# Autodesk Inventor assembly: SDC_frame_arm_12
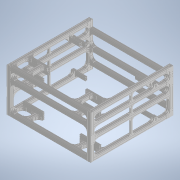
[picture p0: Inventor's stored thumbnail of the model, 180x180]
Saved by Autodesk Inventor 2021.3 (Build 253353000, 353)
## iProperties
Created: 2022-02
Part Number: SDC_frame_arm_12
Description: CAx-IF Rec.Pracs.---Model Styling and Organization---1.2---2011-12-15
Document SubType Name: Assembly
Designer: kengo
Sending System: 3D_Kernel_IO2017 Sp2 by CT CoreTechnologie
Preprocessor: STEP Interface 2017 Sp2 by CT CoreTechnologie
Title: SDC_frame_arm_12.stp
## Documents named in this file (150)
- C:\Users\kengo\Documents\S2S_frame\SDC345\frame_misumi_ver12\SDC_frame_arm_12.iam
- C:\Users\kengo\Documents\S2S_frame\SDC345\frame_misumi_ver12\HBLFSDW8-90-SET(1).iam
- C:\Users\kengo\Documents\S2S_frame\SDC345\frame_misumi_ver12\HBLFSDW8-90-SET(2).iam
- C:\Users\kengo\Documents\S2S_frame\SDC345\frame_misumi_ver12\HBLFSDW8-90-SET(3).iam
- C:\Users\kengo\Documents\S2S_frame\SDC345\frame_misumi_ver12\HBLFSDW8-90-SET(4).iam
- C:\Users\kengo\Documents\S2S_frame\SDC345\frame_misumi_ver12\HBLFSDW8-90-SET(5).iam
- C:\Users\kengo\Documents\S2S_frame\SDC345\frame_misumi_ver12\HBLFSDW8-90-SET(6).iam
- C:\Users\kengo\Documents\S2S_frame\SDC345\frame_misumi_ver12\HBLFSDW8-90-SET(7).iam
- C:\Users\kengo\Documents\S2S_frame\SDC345\frame_misumi_ver12\HBLFSDW8-90-SET(8).iam
- C:\Users\kengo\Documents\S2S_frame\SDC345\frame_misumi_ver12\HBLFSDW8-90-SET(9).iam
- C:\Users\kengo\Documents\S2S_frame\SDC345\frame_misumi_ver12\HBLFSDW8-90-SET(10).iam
- C:\Users\kengo\Documents\S2S_frame\SDC345\frame_misumi_ver12\HBLFSDW8-90-SET(11).iam
- C:\Users\kengo\Documents\S2S_frame\SDC345\frame_misumi_ver12\HBLFSDW8-90-SET(12).iam
- C:\Users\kengo\Documents\S2S_frame\SDC345\frame_misumi_ver12\HBLFSDW8-90-SET(13).iam
- C:\Users\kengo\Documents\S2S_frame\SDC345\frame_misumi_ver12\HBLFSDW8-90-SET(14).iam
- C:\Users\kengo\Documents\S2S_frame\SDC345\frame_misumi_ver12\HBLFSDW8-90-SET(15).iam
- C:\Users\kengo\Documents\S2S_frame\SDC345\frame_misumi_ver12\HBLFSDW8-90-SET(16).iam
- C:\Users\kengo\Documents\S2S_frame\SDC345\frame_misumi_ver12\HBLFSDW8-90-SET(17).iam
- C:\Users\kengo\Documents\S2S_frame\SDC345\frame_misumi_ver12\HBLFSDW8-90-SET(18).iam
- C:\Users\kengo\Documents\S2S_frame\SDC345\frame_misumi_ver12\HBLFSDW8-90-SET(19).iam
- C:\Users\kengo\Documents\S2S_frame\SDC345\frame_misumi_ver12\HBLFSDW8-90-SET(20).iam
- C:\Users\kengo\Documents\S2S_frame\SDC345\frame_misumi_ver12\HBLFSDW8-90-SET(21).iam
- C:\Users\kengo\Documents\S2S_frame\SDC345\frame_misumi_ver12\GNFS8-9090-1910.ipt
- C:\Users\kengo\Documents\S2S_frame\SDC345\frame_misumi_ver12\GNFS8-9090-1940.ipt
- C:\Users\kengo\Documents\S2S_frame\SDC345\frame_misumi_ver12\GNFS8-9090-1090.ipt
- C:\Users\kengo\Documents\S2S_frame\SDC345\frame_misumi_ver12\HBLFSDW8-90-SET(22).iam
- C:\Users\kengo\Documents\S2S_frame\SDC345\frame_misumi_ver12\HPTTD8-45-SET(1).iam
- C:\Users\kengo\Documents\S2S_frame\SDC345\frame_misumi_ver12\HPTTD8-45-SET(2).iam
- C:\Users\kengo\Documents\S2S_frame\SDC345\frame_misumi_ver12\HPTTD8-45-SET(3).iam
- C:\Users\kengo\Documents\S2S_frame\SDC345\frame_misumi_ver12\HPTLD8-45-SET(1).iam
- C:\Users\kengo\Documents\S2S_frame\SDC345\frame_misumi_ver12\HPTLD8-45-SET(2).iam
- C:\Users\kengo\Documents\S2S_frame\SDC345\frame_misumi_ver12\HPTTD8-45-SET(4).iam
- C:\Users\kengo\Documents\S2S_frame\SDC345\frame_misumi_ver12\HPTLD8-45-SET(3).iam
- C:\Users\kengo\Documents\S2S_frame\SDC345\frame_misumi_ver12\HPTLD8-45-SET(4).iam
- C:\Users\kengo\Documents\S2S_frame\SDC345\frame_misumi_ver12\HBLFSDW8-90-SET(23).iam
- C:\Users\kengo\Documents\S2S_frame\SDC345\frame_misumi_ver12\HBLFSDW8-90-SET(24).iam
- C:\Users\kengo\Documents\S2S_frame\SDC345\frame_misumi_ver12\HBLFSDW8-90-SET(25).iam
- C:\Users\kengo\Documents\S2S_frame\SDC345\frame_misumi_ver12\HBLFSDW8-90-SET(26).iam
- C:\Users\kengo\Documents\S2S_frame\SDC345\frame_misumi_ver12\HBLFSDW8-90-SET(27).iam
- C:\Users\kengo\Documents\S2S_frame\SDC345\frame_misumi_ver12\HBLFSDW8-90-SET(28).iam
- C:\Users\kengo\Documents\S2S_frame\SDC345\frame_misumi_ver12\HBLFSDW8-90-SET(29).iam
- C:\Users\kengo\Documents\S2S_frame\SDC345\frame_misumi_ver12\HBLFSDW8-90-SET(30).iam
- C:\Users\kengo\Documents\S2S_frame\SDC345\frame_misumi_ver12\HBLFSDW8-90-SET(31).iam
- C:\Users\kengo\Documents\S2S_frame\SDC345\frame_misumi_ver12\HBLFSDW8-90-SET(32).iam
- C:\Users\kengo\Documents\S2S_frame\SDC345\frame_misumi_ver12\HBLFSDW8-90-SET(33).iam
- C:\Users\kengo\Documents\S2S_frame\SDC345\frame_misumi_ver12\HBLFSDW8-90-SET(34).iam
- C:\Users\kengo\Documents\S2S_frame\SDC345\frame_misumi_ver12\HBLFSDW8-90-SET(35).iam
- C:\Users\kengo\Documents\S2S_frame\SDC345\frame_misumi_ver12\HBLFSDW8-90-SET(36).iam
- C:\Users\kengo\Documents\S2S_frame\SDC345\frame_misumi_ver12\HBLFSDW8-90-SET(37).iam
- C:\Users\kengo\Documents\S2S_frame\SDC345\frame_misumi_ver12\HBLFSDW8-90-SET(38).iam
- C:\Users\kengo\Documents\S2S_frame\SDC345\frame_misumi_ver12\HBLFSDW8-90-SET(39).iam
- C:\Users\kengo\Documents\S2S_frame\SDC345\frame_misumi_ver12\HBLFSDW8-90-SET(40).iam
- C:\Users\kengo\Documents\S2S_frame\SDC345\frame_misumi_ver12\HBLFSDW8-90-SET(41).iam
- C:\Users\kengo\Documents\S2S_frame\SDC345\frame_misumi_ver12\HBLFSDW8-90-SET(42).iam
- C:\Users\kengo\Documents\S2S_frame\SDC345\frame_misumi_ver12\HBLFSDW8-90-SET(43).iam
- C:\Users\kengo\Documents\S2S_frame\SDC345\frame_misumi_ver12\HBLFSDW8-90-SET(44).iam
- C:\Users\kengo\Documents\S2S_frame\SDC345\frame_misumi_ver12\HPTSD8-45-SET(1).iam
- C:\Users\kengo\Documents\S2S_frame\SDC345\frame_misumi_ver12\HBLFSDW8-90-SET(45).iam
- C:\Users\kengo\Documents\S2S_frame\SDC345\frame_misumi_ver12\HPTSD8-45-SET(2).iam
- C:\Users\kengo\Documents\S2S_frame\SDC345\frame_misumi_ver12\HPTSD8-45-SET(3).iam
- C:\Users\kengo\Documents\S2S_frame\SDC345\frame_misumi_ver12\HPTSD8-45-SET(4).iam
- C:\Users\kengo\Documents\S2S_frame\SDC345\frame_misumi_ver12\GNFS8-4590-360-RTP.ipt
- C:\Users\kengo\Documents\S2S_frame\SDC345\frame_misumi_ver12\HBLFSDW8-90-SET(46).iam
- C:\Users\kengo\Documents\S2S_frame\SDC345\frame_misumi_ver12\HBLFSDW8-90-SET(47).iam
- C:\Users\kengo\Documents\S2S_frame\SDC345\frame_misumi_ver12\HBLFSDW8-90-SET(48).iam
- C:\Users\kengo\Documents\S2S_frame\SDC345\frame_misumi_ver12\HBLFSDW8-90-SET(49).iam
- C:\Users\kengo\Documents\S2S_frame\SDC345\frame_misumi_ver12\HBLFSDW8-90-SET(50).iam
- C:\Users\kengo\Documents\S2S_frame\SDC345\frame_misumi_ver12\GNFS8-4590-360-LTP.ipt
- C:\Users\kengo\Documents\S2S_frame\SDC345\frame_misumi_ver12\HBLFSN8-45-SET(1).iam
- C:\Users\kengo\Documents\S2S_frame\SDC345\frame_misumi_ver12\HBLFSDW8-90-SET(51).iam
- C:\Users\kengo\Documents\S2S_frame\SDC345\frame_misumi_ver12\HBLFSDW8-90-SET(52).iam
- C:\Users\kengo\Documents\S2S_frame\SDC345\frame_misumi_ver12\HBLFSDW8-90-SET(53).iam
- C:\Users\kengo\Documents\S2S_frame\SDC345\frame_misumi_ver12\GNFS8-4545-180.ipt
- C:\Users\kengo\Documents\S2S_frame\SDC345\frame_misumi_ver12\HBLFSN8-45-SET(2).iam
- C:\Users\kengo\Documents\S2S_frame\SDC345\frame_misumi_ver12\HBLFSN8-45-SET(3).iam
- C:\Users\kengo\Documents\S2S_frame\SDC345\frame_misumi_ver12\HBLFSN8-45-SET(4).iam
- C:\Users\kengo\Documents\S2S_frame\SDC345\frame_misumi_ver12\HBLFSN8-45-SET(5).iam
- C:\Users\kengo\Documents\S2S_frame\SDC345\frame_misumi_ver12\GNFS8-4545-185.ipt
- C:\Users\kengo\Documents\S2S_frame\SDC345\frame_misumi_ver12\HBLFSN8-45-SET(6).iam
- C:\Users\kengo\Documents\S2S_frame\SDC345\frame_misumi_ver12\HBLFSN8-45-SET(7).iam
- C:\Users\kengo\Documents\S2S_frame\SDC345\frame_misumi_ver12\HBLFSN8-45-SET(8).iam
- C:\Users\kengo\Documents\S2S_frame\SDC345\frame_misumi_ver12\HBLFSN8-45-SET(9).iam
- C:\Users\kengo\Documents\S2S_frame\SDC345\frame_misumi_ver12\GNFS8-4545-365.ipt
- C:\Users\kengo\Documents\S2S_frame\SDC345\frame_misumi_ver12\HBLFSN8-45-SET(10).iam
- C:\Users\kengo\Documents\S2S_frame\SDC345\frame_misumi_ver12\HBLFSN8-45-SET(11).iam
- C:\Users\kengo\Documents\S2S_frame\SDC345\frame_misumi_ver12\HBLFSN8-45-SET(12).iam
- C:\Users\kengo\Documents\S2S_frame\SDC345\frame_misumi_ver12\HBLFSN8-45-SET(13).iam
- C:\Users\kengo\Documents\S2S_frame\SDC345\frame_misumi_ver12\HBLFSN8-45-SET(14).iam
- C:\Users\kengo\Documents\S2S_frame\SDC345\frame_misumi_ver12\HBLFSN8-45-SET(15).iam
- C:\Users\kengo\Documents\S2S_frame\SDC345\frame_misumi_ver12\HBLFSN8-45-SET(16).iam
- C:\Users\kengo\Documents\S2S_frame\SDC345\frame_misumi_ver12\HBLFSN8-45-SET(17).iam
- C:\Users\kengo\Documents\S2S_frame\SDC345\frame_misumi_ver12\HBLFSN8-45-SET(18).iam
- C:\Users\kengo\Documents\S2S_frame\SDC345\frame_misumi_ver12\HBLFSN8-45-SET(19).iam
- C:\Users\kengo\Documents\S2S_frame\SDC345\frame_misumi_ver12\HBLFSN8-45-SET(20).iam
- C:\Users\kengo\Documents\S2S_frame\SDC345\frame_misumi_ver12\HBLFSN8-45-SET(21).iam
- C:\Users\kengo\Documents\S2S_frame\SDC345\frame_misumi_ver12\HBLFSN8-45-SET(22).iam
- C:\Users\kengo\Documents\S2S_frame\SDC345\frame_misumi_ver12\HBLFSN8-45-SET(23).iam
- C:\Users\kengo\Documents\S2S_frame\SDC345\frame_misumi_ver12\HBLFSN8-45-SET(24).iam
- C:\Users\kengo\Documents\S2S_frame\SDC345\frame_misumi_ver12\HBLFSN8-45-SET(25).iam
- C:\Users\kengo\Documents\S2S_frame\SDC345\frame_misumi_ver12\HBLFSN8-45-SET(26).iam
- C:\Users\kengo\Documents\S2S_frame\SDC345\frame_misumi_ver12\HBLFSN8-45-SET(27).iam
- C:\Users\kengo\Documents\S2S_frame\SDC345\frame_misumi_ver12\HBLFSN8-45-SET(28).iam
- C:\Users\kengo\Documents\S2S_frame\SDC345\frame_misumi_ver12\HBLFSDW8-90-SET(54).iam
- C:\Users\kengo\Documents\S2S_frame\SDC345\frame_misumi_ver12\HBLFSDW8-90-SET(55).iam
- C:\Users\kengo\Documents\S2S_frame\SDC345\frame_misumi_ver12\HFS8-45180-500.ipt
- C:\Users\kengo\Documents\S2S_frame\SDC345\frame_misumi_ver12\HBLFSDW8-90-SET(56).iam
- C:\Users\kengo\Documents\S2S_frame\SDC345\frame_misumi_ver12\HBLFSDW8-90-SET(57).iam
- C:\Users\kengo\Documents\S2S_frame\SDC345\frame_misumi_ver12\GNFS8-9090-225.ipt
- C:\Users\kengo\Documents\S2S_frame\SDC345\frame_misumi_ver12\HBLFSDW8-90-SET(58).iam
- C:\Users\kengo\Documents\S2S_frame\SDC345\frame_misumi_ver12\HBLFSDW8-90-SET(59).iam
- C:\Users\kengo\Documents\S2S_frame\SDC345\frame_misumi_ver12\HBLFSDW8-90-SET(60).iam
- C:\Users\kengo\Documents\S2S_frame\SDC345\frame_misumi_ver12\HBLFSDW8-90-SET(61).iam
- C:\Users\kengo\Documents\S2S_frame\SDC345\frame_misumi_ver12\HBLFSDW8-90-SET(62).iam
- C:\Users\kengo\Documents\S2S_frame\SDC345\frame_misumi_ver12\HBLFSDW8-90-SET(63).iam
- C:\Users\kengo\Documents\S2S_frame\SDC345\frame_misumi_ver12\HBLFSDW8-90-SET(64).iam
- C:\Users\kengo\Documents\S2S_frame\SDC345\frame_misumi_ver12\HBLFSDW8-90-SET(65).iam
- C:\Users\kengo\Documents\S2S_frame\SDC345\frame_misumi_ver12\HBLFSDW8-90-SET(66).iam
- C:\Users\kengo\Documents\S2S_frame\SDC345\frame_misumi_ver12\HBLFSDW8-90-SET(67).iam
- C:\Users\kengo\Documents\S2S_frame\SDC345\frame_misumi_ver12\HBLFSDW8-90-SET(68).iam
- C:\Users\kengo\Documents\S2S_frame\SDC345\frame_misumi_ver12\HBLFSDW8-90-SET(69).iam
- C:\Users\kengo\Documents\S2S_frame\SDC345\frame_misumi_ver12\HBLFSDW8-90-SET(70).iam
- C:\Users\kengo\Documents\S2S_frame\SDC345\frame_misumi_ver12\HBLFSDW8-90-SET(71).iam
- C:\Users\kengo\Documents\S2S_frame\SDC345\frame_misumi_ver12\HBLFSDW8-90-SET(72).iam
- C:\Users\kengo\Documents\S2S_frame\SDC345\frame_misumi_ver12\HBLFSDW8-90-SET(73).iam
- C:\Users\kengo\Documents\S2S_frame\SDC345\frame_misumi_ver12\HBLFSDW8-90-SET(74).iam
- C:\Users\kengo\Documents\S2S_frame\SDC345\frame_misumi_ver12\HBLFSDW8-90-SET(75).iam
- C:\Users\kengo\Documents\S2S_frame\SDC345\frame_misumi_ver12\HBLFSDW8-90-SET(76).iam
- C:\Users\kengo\Documents\S2S_frame\SDC345\frame_misumi_ver12\HBLFSDW8-90-SET(77).iam
- C:\Users\kengo\Documents\S2S_frame\SDC345\frame_misumi_ver12\HBLFSDW8-90-SET(78).iam
- C:\Users\kengo\Documents\S2S_frame\SDC345\frame_misumi_ver12\HBLFSDW8-90-SET(79).iam
- C:\Users\kengo\Documents\S2S_frame\SDC345\frame_misumi_ver12\GNFS8-9090-369.ipt
- C:\Users\kengo\Documents\S2S_frame\SDC345\frame_misumi_ver12\HBLFSDW8-90-SET(80).iam
- C:\Users\kengo\Documents\S2S_frame\SDC345\frame_misumi_ver12\HBLFSDW8-90-SET(81).iam
- C:\Users\kengo\Documents\S2S_frame\SDC345\frame_misumi_ver12\HBLFSDW8-90-SET(82).iam
- C:\Users\kengo\Documents\S2S_frame\SDC345\frame_misumi_ver12\HBLFSDW8-90-SET(83).iam
- C:\Users\kengo\Documents\S2S_frame\SDC345\frame_misumi_ver12\HBLFSDW8-90-SET(84).iam
- C:\Users\kengo\Documents\S2S_frame\SDC345\frame_misumi_ver12\HBLFSDW8-90-SET(85).iam
- C:\Users\kengo\Documents\S2S_frame\SDC345\frame_misumi_ver12\HBLFSDW8-90-SET(86).iam
- C:\Users\kengo\Documents\S2S_frame\SDC345\frame_misumi_ver12\HBLFSDW8-90-SET(87).iam
- C:\Users\kengo\Documents\S2S_frame\SDC345\frame_misumi_ver12\HBLFSDW8-90-SET(88).iam
- C:\Users\kengo\Documents\S2S_frame\SDC345\frame_misumi_ver12\HBLFSDW8-90-SET(89).iam
- C:\Users\kengo\Documents\S2S_frame\SDC345\frame_misumi_ver12\HBLFSN8-45-SET(29).iam
- C:\Users\kengo\Documents\S2S_frame\SDC345\frame_misumi_ver12\HBLFSN8-45-SET(30).iam
- C:\Users\kengo\Documents\S2S_frame\SDC345\frame_misumi_ver12\HBLFSDW8-90-SET(90).iam
- C:\Users\kengo\Documents\S2S_frame\SDC345\frame_misumi_ver12\HBLFSDW8-90-SET(91).iam
- C:\Users\kengo\Documents\S2S_frame\SDC345\frame_misumi_ver12\HBLFSDW8-90-SET(92).iam
- C:\Users\kengo\Documents\S2S_frame\SDC345\frame_misumi_ver12\HBLFSDW8-90-SET(93).iam
- C:\Users\kengo\Documents\S2S_frame\SDC345\frame_misumi_ver12\HBLFSDW8-90-SET(94).iam
- C:\Users\kengo\Documents\S2S_frame\SDC345\frame_misumi_ver12\HBLFSDW8-90-SET(95).iam
- C:\Users\kengo\Documents\S2S_frame\SDC345\frame_misumi_ver12\HBLFSDW8-90-SET(96).iam
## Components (180 placed, 149 different names)
1. HBLFSDW8-90-SET(1) [sub-assembly]
2. HBLFSDW8-90-SET(2) [sub-assembly]
3. HBLFSDW8-90-SET(3) [sub-assembly]
4. HBLFSDW8-90-SET(4) [sub-assembly]
5. HBLFSDW8-90-SET(5) [sub-assembly]
6. HBLFSDW8-90-SET(6) [sub-assembly]
7. HBLFSDW8-90-SET(7) [sub-assembly]
8. HBLFSDW8-90-SET(8) [sub-assembly]
9. HBLFSDW8-90-SET(9) [sub-assembly]
10. HBLFSDW8-90-SET(10) [sub-assembly]
11. HBLFSDW8-90-SET(11) [sub-assembly]
12. HBLFSDW8-90-SET(12) [sub-assembly]
13. HBLFSDW8-90-SET(13) [sub-assembly]
14. HBLFSDW8-90-SET(14) [sub-assembly]
15. HBLFSDW8-90-SET(15) [sub-assembly]
16. HBLFSDW8-90-SET(16) [sub-assembly]
17. HBLFSDW8-90-SET(17) [sub-assembly]
18. HBLFSDW8-90-SET(18) [sub-assembly]
19. HBLFSDW8-90-SET(19) [sub-assembly]
20. HBLFSDW8-90-SET(20) [sub-assembly]
21. HBLFSDW8-90-SET(21) [sub-assembly]
22. GNFS8-9090-1910
23. GNFS8-9090-1910:1
24. GNFS8-9090-1940
25. GNFS8-9090-1940:1
26. GNFS8-9090-1090 — フラッシュ:1, メイト:3, メイト:6
27. GNFS8-9090-1090:1 — メイト:1, フラッシュ:2, メイト:5, フラッシュ:5
28. GNFS8-9090-1940:2 — フラッシュ:1, メイト:1, フラッシュ:2, メイト:2, フラッシュ:3, メイト:4, フラッシュ:4, メイト:6
29. GNFS8-9090-1910:2
30. GNFS8-9090-1910:3
31. GNFS8-9090-1910:4
32. GNFS8-9090-1910:5 — フラッシュ:5
33. GNFS8-9090-1910:6
34. GNFS8-9090-1910:7
35. GNFS8-9090-1090:2
36. GNFS8-9090-1090:3
37. GNFS8-9090-1940:3
38. GNFS8-9090-1940:4
39. GNFS8-9090-1940:5
40. HBLFSDW8-90-SET(22) [sub-assembly]
41. HPTTD8-45-SET(1) [sub-assembly]
42. HPTTD8-45-SET(2) [sub-assembly]
43. HPTTD8-45-SET(3) [sub-assembly]
44. HPTLD8-45-SET(1) [sub-assembly]
45. HPTLD8-45-SET(2) [sub-assembly]
46. HPTTD8-45-SET(4) [sub-assembly]
47. HPTLD8-45-SET(3) [sub-assembly]
48. HPTLD8-45-SET(4) [sub-assembly]
49. HBLFSDW8-90-SET(23) [sub-assembly]
50. HBLFSDW8-90-SET(24) [sub-assembly]
51. HBLFSDW8-90-SET(25) [sub-assembly]
52. HBLFSDW8-90-SET(26) [sub-assembly]
53. HBLFSDW8-90-SET(27) [sub-assembly]
54. HBLFSDW8-90-SET(28) [sub-assembly]
55. HBLFSDW8-90-SET(29) [sub-assembly]
56. HBLFSDW8-90-SET(30) [sub-assembly]
57. HBLFSDW8-90-SET(31) [sub-assembly]
58. HBLFSDW8-90-SET(32) [sub-assembly]
59. HBLFSDW8-90-SET(33) [sub-assembly]
60. HBLFSDW8-90-SET(34) [sub-assembly]
61. HBLFSDW8-90-SET(35) [sub-assembly]
62. HBLFSDW8-90-SET(36) [sub-assembly]
63. HBLFSDW8-90-SET(37) [sub-assembly]
64. HBLFSDW8-90-SET(38) [sub-assembly]
65. HBLFSDW8-90-SET(39) [sub-assembly] — メイト:2, フラッシュ:3, メイト:3
66. HBLFSDW8-90-SET(40) [sub-assembly] — メイト:4, フラッシュ:4, メイト:5
67. HBLFSDW8-90-SET(41) [sub-assembly]
68. HBLFSDW8-90-SET(42) [sub-assembly]
69. HBLFSDW8-90-SET(43) [sub-assembly]
70. HBLFSDW8-90-SET(44) [sub-assembly]
71. HPTSD8-45-SET(1) [sub-assembly]
72. HBLFSDW8-90-SET(45) [sub-assembly]
73. HPTSD8-45-SET(2) [sub-assembly]
74. HPTSD8-45-SET(3) [sub-assembly]
75. HPTSD8-45-SET(4) [sub-assembly]
76. GNFS8-4590-360-RTP
77. HBLFSDW8-90-SET(46) [sub-assembly]
78. HBLFSDW8-90-SET(47) [sub-assembly]
79. GNFS8-4590-360-RTP:1
80. HBLFSDW8-90-SET(48) [sub-assembly]
81. HBLFSDW8-90-SET(49) [sub-assembly]
82. GNFS8-4590-360-RTP:2
83. HBLFSDW8-90-SET(50) [sub-assembly]
84. GNFS8-4590-360-LTP
85. GNFS8-4590-360-LTP:1
86. GNFS8-4590-360-LTP:2
87. HBLFSN8-45-SET(1) [sub-assembly]
88. HBLFSDW8-90-SET(51) [sub-assembly]
89. HBLFSDW8-90-SET(52) [sub-assembly]
90. HBLFSDW8-90-SET(53) [sub-assembly]
91. GNFS8-4545-180
92. HBLFSN8-45-SET(2) [sub-assembly]
93. HBLFSN8-45-SET(3) [sub-assembly]
94. HBLFSN8-45-SET(4) [sub-assembly]
95. HBLFSN8-45-SET(5) [sub-assembly]
96. GNFS8-4545-185
97. HBLFSN8-45-SET(6) [sub-assembly]
98. HBLFSN8-45-SET(7) [sub-assembly]
99. HBLFSN8-45-SET(8) [sub-assembly]
100. HBLFSN8-45-SET(9) [sub-assembly]
101. GNFS8-4545-365
102. HBLFSN8-45-SET(10) [sub-assembly]
103. HBLFSN8-45-SET(11) [sub-assembly]
104. HBLFSN8-45-SET(12) [sub-assembly]
105. HBLFSN8-45-SET(13) [sub-assembly]
106. GNFS8-4545-365:1
107. HBLFSN8-45-SET(14) [sub-assembly]
108. HBLFSN8-45-SET(15) [sub-assembly]
109. HBLFSN8-45-SET(16) [sub-assembly]
110. HBLFSN8-45-SET(17) [sub-assembly]
111. GNFS8-4545-185:1
112. HBLFSN8-45-SET(18) [sub-assembly]
113. HBLFSN8-45-SET(19) [sub-assembly]
114. HBLFSN8-45-SET(20) [sub-assembly]
115. HBLFSN8-45-SET(21) [sub-assembly]
116. GNFS8-4545-180:1
117. HBLFSN8-45-SET(22) [sub-assembly]
118. HBLFSN8-45-SET(23) [sub-assembly]
119. HBLFSN8-45-SET(24) [sub-assembly]
120. HBLFSN8-45-SET(25) [sub-assembly]
121. HBLFSN8-45-SET(26) [sub-assembly]
122. HBLFSN8-45-SET(27) [sub-assembly]
123. HBLFSN8-45-SET(28) [sub-assembly]
124. HBLFSDW8-90-SET(54) [sub-assembly]
125. HBLFSDW8-90-SET(55) [sub-assembly]
126. HFS8-45180-500
127. HBLFSDW8-90-SET(56) [sub-assembly]
128. HBLFSDW8-90-SET(57) [sub-assembly]
129. GNFS8-9090-225
130. HBLFSDW8-90-SET(58) [sub-assembly]
131. HBLFSDW8-90-SET(59) [sub-assembly]
132. HBLFSDW8-90-SET(60) [sub-assembly]
133. HFS8-45180-500:1
134. HBLFSDW8-90-SET(61) [sub-assembly]
135. HBLFSDW8-90-SET(62) [sub-assembly]
136. GNFS8-9090-225:1
137. HBLFSDW8-90-SET(63) [sub-assembly]
138. HBLFSDW8-90-SET(64) [sub-assembly]
139. HBLFSDW8-90-SET(65) [sub-assembly]
140. HBLFSDW8-90-SET(66) [sub-assembly]
141. HBLFSDW8-90-SET(67) [sub-assembly]
142. HFS8-45180-500:2
143. HBLFSDW8-90-SET(68) [sub-assembly]
144. HBLFSDW8-90-SET(69) [sub-assembly]
145. GNFS8-9090-225:2
146. HBLFSDW8-90-SET(70) [sub-assembly]
147. HBLFSDW8-90-SET(71) [sub-assembly]
148. HBLFSDW8-90-SET(72) [sub-assembly]
149. HFS8-45180-500:3
150. HBLFSDW8-90-SET(73) [sub-assembly]
151. HBLFSDW8-90-SET(74) [sub-assembly]
152. GNFS8-9090-225:3
153. HBLFSDW8-90-SET(75) [sub-assembly]
154. HBLFSDW8-90-SET(76) [sub-assembly]
155. HBLFSDW8-90-SET(77) [sub-assembly]
156. HBLFSDW8-90-SET(78) [sub-assembly]
157. HBLFSDW8-90-SET(79) [sub-assembly]
158. HFS8-45180-500:4
159. GNFS8-9090-369
160. HBLFSDW8-90-SET(80) [sub-assembly]
161. HBLFSDW8-90-SET(81) [sub-assembly]
162. HFS8-45180-500:5
163. GNFS8-9090-369:1
164. HBLFSDW8-90-SET(82) [sub-assembly]
165. HBLFSDW8-90-SET(83) [sub-assembly]
166. HBLFSDW8-90-SET(84) [sub-assembly]
167. HBLFSDW8-90-SET(85) [sub-assembly]
168. HBLFSDW8-90-SET(86) [sub-assembly]
169. HBLFSDW8-90-SET(87) [sub-assembly]
170. HBLFSDW8-90-SET(88) [sub-assembly]
171. HBLFSDW8-90-SET(89) [sub-assembly]
172. HBLFSN8-45-SET(29) [sub-assembly]
173. HBLFSN8-45-SET(30) [sub-assembly]
174. HBLFSDW8-90-SET(90) [sub-assembly]
175. HBLFSDW8-90-SET(91) [sub-assembly]
176. HBLFSDW8-90-SET(92) [sub-assembly]
177. HBLFSDW8-90-SET(93) [sub-assembly]
178. HBLFSDW8-90-SET(94) [sub-assembly]
179. HBLFSDW8-90-SET(95) [sub-assembly]
180. HBLFSDW8-90-SET(96) [sub-assembly]
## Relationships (11: Mate 6, Flush 5)
- フラッシュ:1 [Flush]: GNFS8-9090-1090 ↔ GNFS8-9090-1940:2
- メイト:1 [Mate]: GNFS8-9090-1090:1 ↔ GNFS8-9090-1940:2
- フラッシュ:2 [Flush]: GNFS8-9090-1090:1 ↔ GNFS8-9090-1940:2
- メイト:2 [Mate]: GNFS8-9090-1940:2 ↔ HBLFSDW8-90-SET(39)
- フラッシュ:3 [Flush]: GNFS8-9090-1940:2 ↔ HBLFSDW8-90-SET(39)
- メイト:3 [Mate]: GNFS8-9090-1090 ↔ HBLFSDW8-90-SET(39)
- メイト:4 [Mate]: GNFS8-9090-1940:2 ↔ HBLFSDW8-90-SET(40)
- フラッシュ:4 [Flush]: GNFS8-9090-1940:2 ↔ HBLFSDW8-90-SET(40)
- メイト:5 [Mate]: GNFS8-9090-1090:1 ↔ HBLFSDW8-90-SET(40)
- メイト:6 [Mate]: GNFS8-9090-1090 ↔ GNFS8-9090-1940:2
- フラッシュ:5 [Flush]: GNFS8-9090-1090:1 ↔ GNFS8-9090-1910:5
